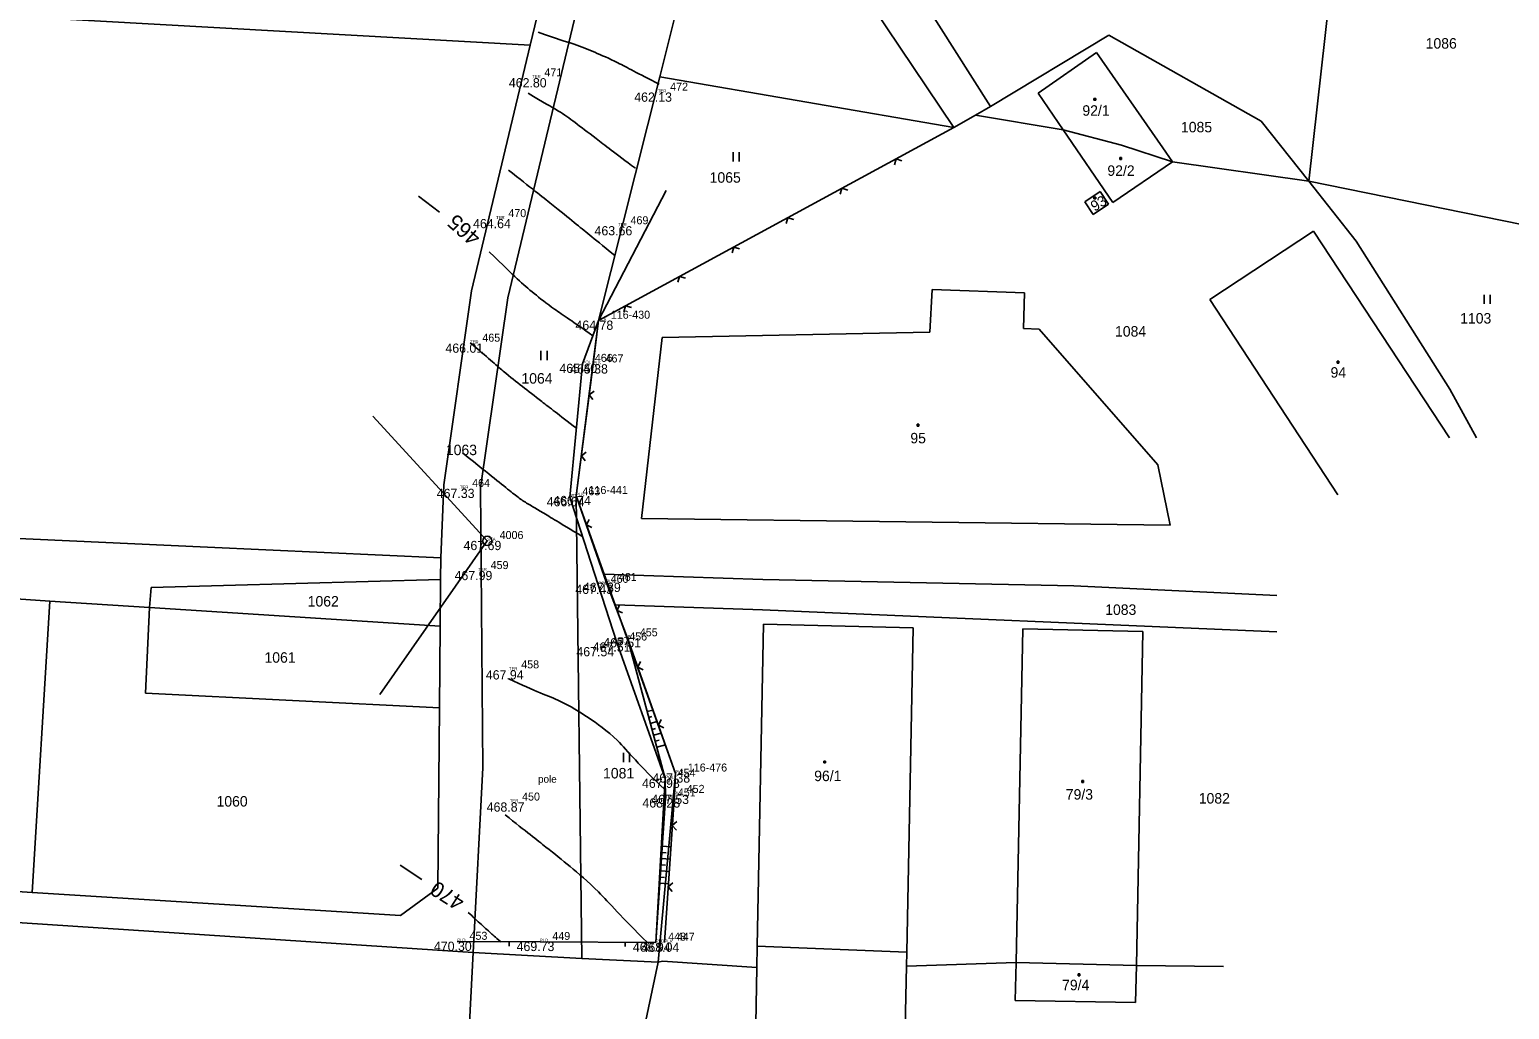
# Model space of a CAD drawing. Extents: x -604848 to -603227, y -1111879 to -1109838.
# Drawn here: x -603652.8 to -603412.5, y -1110124.8 to -1109965.7 of the extents above; entities that cross this region are included whole.
import ezdxf

# ---------------------------------------------------------------- set-up
doc = ezdxf.new("R2010")
doc.units = 0
for name, color, linetype in [('1', 7, 'Continuous'), ('10', 7, 'Continuous'), ('14', 7, 'Continuous'), ('15', 7, 'Continuous'), ('18', 7, 'Continuous'), ('19', 7, 'Continuous'), ('20', 7, 'Continuous'), ('23', 7, 'Continuous'), ('25', 7, 'Continuous'), ('4', 7, 'Continuous'), ('5', 7, 'Continuous'), ('7', 7, 'Continuous'), ('8', 7, 'Continuous'), ('9', 7, 'Continuous'), ('Default', 7, 'Continuous')]:
    doc.layers.add(name, color=color, linetype=linetype)

# ---------------------------------------------------------------- blocks, each defined once
blk = doc.blocks.new('Z3060')
at = {"layer": '23'}
for p, q in [((-0.5, 0), (-0.5, 1.5)), ((0.5, 1.5), (0.5, 0))]:
    blk.add_line(p, q, dxfattribs=at)
blk = doc.blocks.new('Z402')
at = {"layer": '25'}
for p, q in [((-0.1, 0.1), (0.2, 0.1)), ((-0.1, -0.2), (-0.1, 0.1)), ((0.2, 0.1), (0.2, -0.2)), ((0.2, -0.2), (-0.1, -0.2))]:
    blk.add_line(p, q, dxfattribs=at)
blk = doc.blocks.new('POINT_DISPLAY')
at = {"layer": 'Default'}
blk.add_line((0, 0), (0, 0), dxfattribs=at)
blk = doc.blocks.new('Z107')
at = {"layer": '5'}
for radius in [0.75, 0.01]:
    blk.add_circle((0, 0), radius, dxfattribs=at)
blk = doc.blocks.new('Z210')
at = {"layer": '4'}
blk.add_line((0, 0), (0, 0.7), dxfattribs=at)
blk = doc.blocks.new('Z212')
at = {"layer": '4'}
for p, q in [((-0.7, 0.7), (0, 0)), ((0, 0), (0.7, 0.7))]:
    blk.add_line(p, q, dxfattribs=at)

msp = doc.modelspace()

# ---------------------------------------------------------------- linework, layer by layer
at = {"layer": '1'}
for p, q in [((-603575.13, -1110009.26), (-603553.85, -1109920.25)), ((-603550.44, -1109973.35), (-603538.61, -1109926.08)), ((-603562.91, -1109932.34), (-603571.51, -1109968.22)), ((-603521.7, -1109938.92), (-603496.72, -1109978.18)), ((-603439.12, -1109937.35), (-603445.06, -1109990.31)), ((-603502.69, -1109981.6), (-603515.89, -1109961.92)), ((-603571.51, -1109968.22), (-603651.94, -1109963.71)), ((-603496.72, -1109978.18), (-603477.49, -1109966.58)), ((-603477.49, -1109966.58), (-603452.79, -1109980.54)), ((-603581.03, -1110008.14), (-603571.51, -1109968.22)), ((-603479.54, -1109969.41), (-603489.02, -1109976.01)), ((-603468.77, -1109984.9), (-603479.54, -1109969.41)), ((-603550.44, -1109973.35), (-603560.4, -1110012.95)), ((-603502.69, -1109981.6), (-603550.44, -1109973.35)), ((-603489.02, -1109976.01), (-603484.94, -1109981.98)), ((-603499.15, -1109979.59), (-603502.69, -1109981.6)), ((-603499.15, -1109979.59), (-603496.72, -1109978.18)), ((-603484.94, -1109981.98), (-603499.15, -1109979.59)), ((-603560.4, -1110012.95), (-603502.69, -1109981.6)), ((-603484.94, -1109981.98), (-603476.89, -1109993.76)), ((-603475.44, -1109984.44), (-603484.94, -1109981.98)), ((-603452.79, -1109980.54), (-603445.06, -1109990.31)), ((-603467.18, -1109987.18), (-603475.44, -1109984.44)), ((-603467.18, -1109987.18), (-603468.77, -1109984.9)), ((-603476.89, -1109993.76), (-603467.18, -1109987.18)), ((-603445.06, -1109990.31), (-603467.18, -1109987.18)), ((-603445.06, -1109990.31), (-603437.33, -1110000.08)), ((-603407.26, -1109997.99), (-603445.06, -1109990.31)), ((-603481.44, -1109993.67), (-603478.94, -1109991.98)), ((-603480.05, -1109995.74), (-603481.44, -1109993.67)), ((-603477.56, -1109994.02), (-603480.05, -1109995.74)), ((-603478.94, -1109991.98), (-603477.56, -1109994.02)), ((-603444.29, -1109998.42), (-603461.11, -1110009.53)), ((-603422.21, -1110031.99), (-603444.29, -1109998.42)), ((-603437.33, -1110000.08), (-603422.13, -1110024.11)), ((-603585.53, -1110039.62), (-603581.03, -1110008.14)), ((-603506.6, -1110014.82), (-603506.2, -1110007.92)), ((-603506.2, -1110007.92), (-603491.24, -1110008.42)), ((-603491.24, -1110008.42), (-603491.39, -1110014.23)), ((-603579.54, -1110040.09), (-603575.13, -1110009.26)), ((-603461.11, -1110009.53), (-603440.32, -1110041.24)), ((-603560.4, -1110012.95), (-603564.02, -1110041.42)), ((-603553.4, -1110045.11), (-603550.07, -1110015.72)), ((-603550.07, -1110015.72), (-603506.6, -1110014.82)), ((-603491.39, -1110014.23), (-603488.83, -1110014.34)), ((-603488.83, -1110014.34), (-603469.55, -1110036.37)), ((-603422.13, -1110024.11), (-603417.79, -1110031.99)), ((-603469.55, -1110036.37), (-603467.58, -1110046.2)), ((-603586.01, -1110051.49), (-603585.53, -1110039.62)), ((-603579.17, -1110085.6), (-603579.54, -1110040.09)), ((-603564.02, -1110041.42), (-603563.1, -1110116.55)), ((-603559.46, -1110054.15), (-603564.02, -1110041.42)), ((-603697.99, -1110046.37), (-603623.89, -1110049.76)), ((-603467.58, -1110046.2), (-603553.4, -1110045.11)), ((-603623.89, -1110049.76), (-603586.01, -1110051.49)), ((-603586.06, -1110055.02), (-603586.01, -1110051.49)), ((-603557.69, -1110059.11), (-603559.46, -1110054.15)), ((-603533.7, -1110055), (-603559.46, -1110054.15)), ((-603649.49, -1110058.51), (-603706.68, -1110054.81)), ((-603633.08, -1110056.3), (-603633.34, -1110059.55)), ((-603586.06, -1110055.02), (-603633.08, -1110056.3)), ((-603586.13, -1110062.6), (-603586.06, -1110055.02)), ((-603483.19, -1110056.04), (-603533.7, -1110055)), ((-603450.23, -1110057.62), (-603483.19, -1110056.04)), ((-603649.49, -1110058.51), (-603652.36, -1110105.82)), ((-603633.34, -1110059.55), (-603649.49, -1110058.51)), ((-603557.69, -1110059.11), (-603533.76, -1110059.92)), ((-603547.89, -1110086.49), (-603557.69, -1110059.11)), ((-603633.97, -1110073.48), (-603633.34, -1110059.55)), ((-603633.34, -1110059.55), (-603586.13, -1110062.6)), ((-603533.76, -1110059.92), (-603450.23, -1110063.52)), ((-603586.13, -1110062.6), (-603586.24, -1110075.83)), ((-603534.61, -1110114.57), (-603533.58, -1110062.24)), ((-603533.58, -1110062.24), (-603509.27, -1110062.85)), ((-603509.27, -1110062.85), (-603510.35, -1110115.55)), ((-603492.59, -1110117.23), (-603491.49, -1110063.03)), ((-603491.49, -1110063.03), (-603471.98, -1110063.43)), ((-603471.98, -1110063.43), (-603473.01, -1110117.69)), ((-603586.24, -1110075.83), (-603633.97, -1110073.48)), ((-603586.47, -1110105.12), (-603586.24, -1110075.83)), ((-603580.73, -1110115.61), (-603579.17, -1110085.6)), ((-603550.69, -1110117.18), (-603547.89, -1110086.49)), ((-603672.88, -1110104.53), (-603652.36, -1110105.82)), ((-603652.36, -1110105.82), (-603592.56, -1110109.59)), ((-603592.56, -1110109.59), (-603586.47, -1110105.12)), ((-603586.55, -1110115.23), (-603661.5, -1110110.29)), ((-603580.73, -1110115.61), (-603586.55, -1110115.23)), ((-603582.11, -1110142.12), (-603580.73, -1110115.61)), ((-603580.73, -1110115.61), (-603563.1, -1110116.55)), ((-603563.1, -1110116.55), (-603550.69, -1110117.18)), ((-603534.68, -1110118), (-603534.61, -1110114.57)), ((-603510.35, -1110115.55), (-603534.61, -1110114.57)), ((-603510.35, -1110115.55), (-603510.4, -1110117.8)), ((-603550.69, -1110117.18), (-603553.98, -1110132.61)), ((-603549.98, -1110116.99), (-603550.69, -1110117.18)), ((-603534.68, -1110118), (-603549.98, -1110116.99)), ((-603535.42, -1110155.37), (-603534.68, -1110118)), ((-603510.4, -1110117.8), (-603511.16, -1110155.92)), ((-603492.59, -1110117.23), (-603510.4, -1110117.8)), ((-603492.59, -1110117.23), (-603492.71, -1110123.38)), ((-603473.01, -1110117.69), (-603492.59, -1110117.23)), ((-603473.18, -1110123.73), (-603473.01, -1110117.69)), ((-603458.9, -1110117.84), (-603473.01, -1110117.69)), ((-603492.71, -1110123.38), (-603473.18, -1110123.73))]:
    msp.add_line(p, q, dxfattribs=at)
at = {"layer": '10'}
for p, q in [((-603560.4, -1110012.95), (-603549.4, -1109991.8)), ((-603562.99, -1110019.96), (-603560.4, -1110012.95)), ((-603565.03, -1110041.62), (-603562.99, -1110019.96)), ((-603560.43, -1110055.85), (-603565.03, -1110041.62)), ((-603557.41, -1110065.21), (-603560.43, -1110055.85)), ((-603549.55, -1110087.35), (-603557.41, -1110065.21)), ((-603549.55, -1110087.35), (-603551.08, -1110113.95))]:
    msp.add_line(p, q, dxfattribs=at)
at = {"layer": '4'}
for p, q in [((-603560.4, -1110012.95), (-603561.26, -1110020.05)), ((-603561.26, -1110020.05), (-603564.02, -1110041.42)), ((-603564.02, -1110041.42), (-603559.1, -1110055.54)), ((-603559.1, -1110055.54), (-603555.69, -1110064.53)), ((-603555.69, -1110064.53), (-603547.89, -1110086.49)), ((-603547.89, -1110086.49), (-603548.08, -1110089.96)), ((-603548.08, -1110089.96), (-603549.68, -1110113.98)), ((-603569.9, -1110113.85), (-603583.35, -1110113.82)), ((-603551.08, -1110113.95), (-603569.9, -1110113.85))]:
    msp.add_line(p, q, dxfattribs=at)
at = {"layer": '5'}
for q in [(-603597.04, -1110028.48), (-603595.92, -1110073.67)]:
    msp.add_line((-603578.46, -1110048.73), q, dxfattribs=at)
at = {"layer": '7'}
for p, q in [((-603586.25, -1109995.36), (-603589.64, -1109992.74)), ((-603549.55, -1110087.35), (-603555.69, -1110064.53)), ((-603549.52, -1110090.54), (-603549.55, -1110087.35)), ((-603551.08, -1110113.95), (-603549.52, -1110090.54)), ((-603589.09, -1110103.71), (-603592.59, -1110101.42))]:
    msp.add_line(p, q, dxfattribs=at)
for points in [[(-603550.53, -1109974.53), (-603554.07, -1109972.8), (-603557.51, -1109970.86), (-603561.13, -1109969.34), (-603564.09, -1109968.09), (-603567.19, -1109967.19), (-603570.22, -1109966.12)], [(-603554.41, -1109988.22), (-603557.74, -1109985.7), (-603561.06, -1109983.18), (-603564.38, -1109980.67), (-603566.71, -1109978.91), (-603569.34, -1109977.57), (-603571.81, -1109976.03)], [(-603557.74, -1110002.37), (-603559.86, -1110000.65), (-603561.98, -1109998.93), (-603564.1, -1109997.2), (-603567.71, -1109994.27), (-603571.37, -1109991.41), (-603575.01, -1109988.51)], [(-603561.32, -1110015.43), (-603564.52, -1110013.11), (-603567.86, -1110010.99), (-603570.93, -1110008.49), (-603573.47, -1110006.41), (-603575.75, -1110004.04), (-603578.16, -1110001.81)], [(-603563.98, -1110030.45), (-603566.91, -1110028.19), (-603569.84, -1110025.92), (-603572.76, -1110023.65), (-603575.68, -1110021.39), (-603578.42, -1110018.92), (-603581.24, -1110016.55)], [(-603562.94, -1110048.07), (-603565.17, -1110046.73), (-603567.39, -1110045.39), (-603569.61, -1110044.05), (-603571.24, -1110043.06), (-603572.91, -1110042.11), (-603574.39, -1110040.92), (-603577.1, -1110038.75), (-603579.8, -1110036.59), (-603582.51, -1110034.42)], [(-603549.65, -1110089.12), (-603553.84, -1110085.2), (-603557.4, -1110080.55), (-603562.23, -1110077.34), (-603566.2, -1110074.7), (-603570.7, -1110073.19), (-603574.94, -1110071.12)], [(-603552.46, -1110113.95), (-603556.71, -1110109.79), (-603560.61, -1110105.24), (-603565.21, -1110101.47), (-603568.63, -1110098.67), (-603572.11, -1110095.97), (-603575.56, -1110093.22)], [(-603576.29, -1110113.84), (-603577.19, -1110113.05), (-603578.09, -1110112.26), (-603578.98, -1110111.46), (-603579.85, -1110110.67), (-603580.7, -1110109.87), (-603581.55, -1110109.07)]]:
    msp.add_open_spline(points, degree=3, dxfattribs=at)
at = {"layer": '8'}
for p, q in [((-603552.48, -1110076.44), (-603551.57, -1110076.2)), ((-603552.22, -1110077.41), (-603551.73, -1110077.27)), ((-603551.96, -1110078.37), (-603550.9, -1110078.08)), ((-603551.7, -1110079.34), (-603551.13, -1110079.18)), ((-603551.45, -1110080.3), (-603550.22, -1110079.97)), ((-603551.19, -1110081.27), (-603550.53, -1110081.09)), ((-603550.93, -1110082.23), (-603549.54, -1110081.86)), ((-603550.1, -1110099.34), (-603549.41, -1110099.38)), ((-603550.04, -1110098.34), (-603548.64, -1110098.43)), ((-603550.3, -1110102.33), (-603548.91, -1110102.42)), ((-603550.24, -1110101.33), (-603549.54, -1110101.38)), ((-603550.17, -1110100.33), (-603548.77, -1110100.43)), ((-603550.43, -1110104.33), (-603549.04, -1110104.42)), ((-603550.37, -1110103.33), (-603549.67, -1110103.38))]:
    msp.add_line(p, q, dxfattribs=at)

# ---------------------------------------------------------------- block references
at = {"layer": '18'}
for p in [(-603571.18, -1109973.58), (-603550.76, -1109975.91), (-603577.04, -1109996.45), (-603557.2, -1109997.61), (-603560.4, -1110012.95), (-603581.27, -1110016.68), (-603562.99, -1110019.96), (-603561.26, -1110020.05), (-603582.92, -1110040.27), (-603565.03, -1110041.62), (-603564.02, -1110041.42), (-603578.46, -1110048.73), (-603579.92, -1110053.61), (-603560.43, -1110055.85), (-603559.1, -1110055.54), (-603560.27, -1110065.98), (-603557.41, -1110065.21), (-603555.69, -1110064.53), (-603574.95, -1110069.74), (-603549.55, -1110087.35), (-603547.89, -1110086.49), (-603548.08, -1110089.96), (-603574.81, -1110091.21), (-603549.52, -1110090.54), (-603583.35, -1110113.82), (-603569.9, -1110113.85), (-603551.08, -1110113.95), (-603549.68, -1110113.98)]:
    msp.add_blockref('POINT_DISPLAY', p, dxfattribs=at)
at = {"layer": '23'}
for p in [(-603538.03, -1109987.09), (-603416.08, -1110010.25), (-603569.25, -1110019.37), (-603555.85, -1110084.65)]:
    msp.add_blockref('Z3060', p, dxfattribs=at)
at = {"layer": '25'}
for p in [(-603479.85, -1109976.98), (-603475.65, -1109986.59), (-603479.85, -1109993), (-603440.34, -1110019.66), (-603508.56, -1110029.89), (-603523.72, -1110084.59), (-603481.81, -1110087.75), (-603482.41, -1110119.16)]:
    msp.add_blockref('Z402', p, dxfattribs=at)
at = {"layer": '4'}
for name, p, xscale, yscale, rotation in [('Z212', (-603512.07, -1109986.7), 0.999998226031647, 0.999998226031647, -151.48776670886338), ('Z212', (-603520.86, -1109991.47), 0.999998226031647, 0.999998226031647, -151.48776670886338), ('Z212', (-603529.64, -1109996.24), 0.999998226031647, 0.999998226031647, -151.48776670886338), ('Z212', (-603538.43, -1110001.02), 0.999998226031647, 0.999998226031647, -151.48776670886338), ('Z212', (-603547.22, -1110005.79), 0.999998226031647, 0.999998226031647, -151.48776670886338), ('Z212', (-603556.01, -1110010.56), 0.999998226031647, 0.999998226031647, -151.48776670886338), ('Z212', (-603561.9, -1110025.01), 0.9999983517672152, 0.9999983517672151, -97.35438528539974), ('Z212', (-603563.18, -1110034.93), 0.9999983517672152, 0.9999983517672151, -97.35438528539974), ('Z212', (-603562.37, -1110046.14), 0.9999955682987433, 0.9999955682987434, -70.77969727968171), ('Z212', (-603557.39, -1110060.03), 0.9999991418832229, 0.9999991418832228, -69.23551304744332), ('Z212', (-603554.02, -1110069.24), 0.9999957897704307, 0.9999957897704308, -70.44849357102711), ('Z212', (-603550.67, -1110078.66), 0.9999957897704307, 0.9999957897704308, -70.44849357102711), ('Z212', (-603548.41, -1110094.95), 0.9999977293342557, 0.9999977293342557, -93.81359564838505), ('Z212', (-603549.07, -1110104.92), 0.9999977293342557, 0.9999977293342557, -93.81359564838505), ('Z210', (-603574.9, -1110113.84), 0.9999974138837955, 0.9999974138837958, 179.8834059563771), ('Z210', (-603556.08, -1110113.93), 0.9999964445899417, 0.9999964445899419, 179.68543453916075)]:
    msp.add_blockref(name, p, dxfattribs=dict(at, xscale=xscale, yscale=yscale, rotation=rotation))
at = {"layer": '5'}
msp.add_blockref('Z107', (-603578.46, -1110048.73), dxfattribs=at)

# ---------------------------------------------------------------- texts
at = {"layer": '14'}
for s, p in [('1086', (-603426.06, -1109968.78)), ('1085', (-603465.8, -1109982.38)), ('1065', (-603542.35, -1109990.56)), ('1103', (-603420.46, -1110013.43)), ('1084', (-603476.51, -1110015.55)), ('1064', (-603572.92, -1110023.19)), ('1063', (-603585.19, -1110034.81)), ('1062', (-603607.63, -1110059.39)), ('1083', (-603478.11, -1110060.75)), ('1061', (-603614.65, -1110068.52)), ('1081', (-603559.66, -1110087.31)), ('1060', (-603622.44, -1110091.88)), ('1082', (-603462.91, -1110091.39))]:
    msp.add_text(s, height=1.7, dxfattribs=at).set_placement(p)
at = {"layer": '15'}
for s, p in [('92/1', (-603481.81, -1109979.68)), ('92/2', (-603477.75, -1109989.45)), ('94', (-603441.51, -1110022.22)), ('95', (-603509.75, -1110032.89)), ('96/1', (-603525.37, -1110087.75)), ('79/3', (-603484.51, -1110090.75)), ('79/4', (-603485.11, -1110121.71))]:
    msp.add_text(s, height=1.7, dxfattribs=at).set_placement(p)
msp.add_text('93', height=1.7, rotation=31.5056, dxfattribs=at).set_placement((-603479.82, -1109995.29))
at = {"layer": '18'}
for s, p in [('TER', (-603571.18, -1109973.58)), ('TER', (-603550.76, -1109975.91)), ('TER', (-603577.04, -1109996.45)), ('TER', (-603557.2, -1109997.61)), ('PLK', (-603560.4, -1110012.95)), ('TER', (-603581.27, -1110016.68)), ('POL', (-603562.99, -1110019.96)), ('PLK', (-603561.26, -1110020.05)), ('TER', (-603582.92, -1110040.27)), ('POL', (-603565.03, -1110041.62)), ('PLK', (-603564.02, -1110041.42)), ('STA', (-603578.46, -1110048.73)), ('TER', (-603579.92, -1110053.61)), ('POL', (-603560.43, -1110055.85)), ('PLK', (-603559.1, -1110055.54)), ('TER', (-603560.27, -1110065.98)), ('POL', (-603557.41, -1110065.21)), ('PLK', (-603555.69, -1110064.53)), ('TER', (-603574.95, -1110069.74)), ('POL', (-603549.55, -1110087.35)), ('PLK', (-603547.89, -1110086.49)), ('TER', (-603549.52, -1110090.54)), ('PLK', (-603548.08, -1110089.96)), ('TER', (-603574.81, -1110091.21)), ('PLD', (-603583.35, -1110113.82)), ('PLD', (-603569.9, -1110113.85)), ('PLD', (-603551.08, -1110113.95)), ('PLK', (-603549.68, -1110113.98))]:
    msp.add_text(s, height=0.5, dxfattribs=at).set_placement(p)
at = {"layer": '19'}
for s, p in [('471', (-603569.18, -1109973.28)), ('472', (-603548.76, -1109975.61)), ('470', (-603575.04, -1109996.15)), ('469', (-603555.2, -1109997.31)), ('116-430', (-603558.4, -1110012.65)), ('465', (-603579.27, -1110016.38)), ('466', (-603560.99, -1110019.66)), ('467', (-603559.26, -1110019.75)), ('464', (-603580.92, -1110039.97)), ('116-441', (-603562.02, -1110041.12)), ('463', (-603563.03, -1110041.32)), ('4006', (-603576.46, -1110048.43)), ('459', (-603577.92, -1110053.31)), ('460', (-603558.43, -1110055.55)), ('461', (-603557.1, -1110055.24)), ('456', (-603555.41, -1110064.91)), ('455', (-603553.69, -1110064.23)), ('457', (-603558.27, -1110065.68)), ('458', (-603572.95, -1110069.44)), ('116-476', (-603545.89, -1110086.19)), ('454', (-603547.55, -1110087.05)), ('450', (-603572.81, -1110090.91)), ('451', (-603547.52, -1110090.24)), ('452', (-603546.08, -1110089.66)), ('453', (-603581.35, -1110113.52)), ('449', (-603567.9, -1110113.55)), ('448', (-603549.08, -1110113.65)), ('447', (-603547.68, -1110113.68))]:
    msp.add_text(s, height=1.3, dxfattribs=at).set_placement(p)
at = {"layer": '20'}
for s, p in [('462.80 ', (-603574.96, -1109975.08)), ('462.13 ', (-603554.6, -1109977.41)), ('464.64 ', (-603580.77, -1109997.95)), ('463.66 ', (-603561.05, -1109999.11)), ('464.78 ', (-603564.14, -1110014.45)), ('466.01 ', (-603585.26, -1110018.18)), ('465.40 ', (-603566.75, -1110021.46)), ('465.38 ', (-603565.01, -1110021.55)), ('467.33 ', (-603586.67, -1110041.77)), ('466.64 ', (-603568.81, -1110043.12)), ('466.74 ', (-603567.77, -1110042.92)), ('467.69 ', (-603582.32, -1110050.23)), ('467.99 ', (-603583.78, -1110055.11)), ('467.43 ', (-603564.17, -1110057.35)), ('467.39 ', (-603562.92, -1110057.04)), ('467.54 ', (-603563.99, -1110067.48)), ('467.51 ', (-603561.35, -1110066.71)), ('467.51 ', (-603559.63, -1110066.03)), ('467.94 ', (-603578.7, -1110071.24)), ('467.93 ', (-603553.34, -1110088.85)), ('467.38 ', (-603551.65, -1110087.99)), ('467.53 ', (-603551.83, -1110091.46)), ('468.87 ', (-603578.56, -1110092.71)), ('468.28 ', (-603553.27, -1110092.04)), ('470.30 ', (-603587.13, -1110115.32)), ('469.73 ', (-603573.7, -1110115.35)), ('468.94 ', (-603554.82, -1110115.45)), ('468.04 ', (-603553.41, -1110115.48))]:
    msp.add_text(s, height=1.5, dxfattribs=at).set_placement(p)
at = {"layer": '7'}
for s, rotation, p in [('465', 138.6, (-603579.33, -1109999.17)), ('470', 147.6, (-603581.94, -1110106.83))]:
    msp.add_text(s, height=2.5, rotation=rotation, dxfattribs=at).set_placement(p)
at = {"layer": '9'}
msp.add_text('pole', height=1.2, dxfattribs=at).set_placement((-603570.22, -1110088.01))

doc.saveas('drawing.dxf')
